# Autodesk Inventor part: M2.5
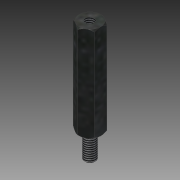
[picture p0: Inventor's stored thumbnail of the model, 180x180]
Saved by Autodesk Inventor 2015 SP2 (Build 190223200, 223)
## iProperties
Created: 2012-08
Part Number: M2.5
Material: Stahl
Document SubType Name: Modeling
Designer: rYan
Mass: 1.74537 g
Surface Area: 3.04272 cm^2
Volume: 0.22234 cm^3
Density: 7.85 g/cm^3
Appearance: Platte
Author: rYan
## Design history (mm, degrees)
derived "Abstandsbolzen Typ B.ipt"
feature "Volumenkörper1::Abstandsbolzen Typ B.ipt"
tag "Bezeichnung1"
node "Volumenkörper1"
other parameters: "SW" = 5, "L" = 22, "d2" = 0, "l_" = 7, "d9" = 118 deg, "GA_" = 2.5, "A_" = 6, "d13" = 0, "d17" = 0.25, "d20" = 45 deg
